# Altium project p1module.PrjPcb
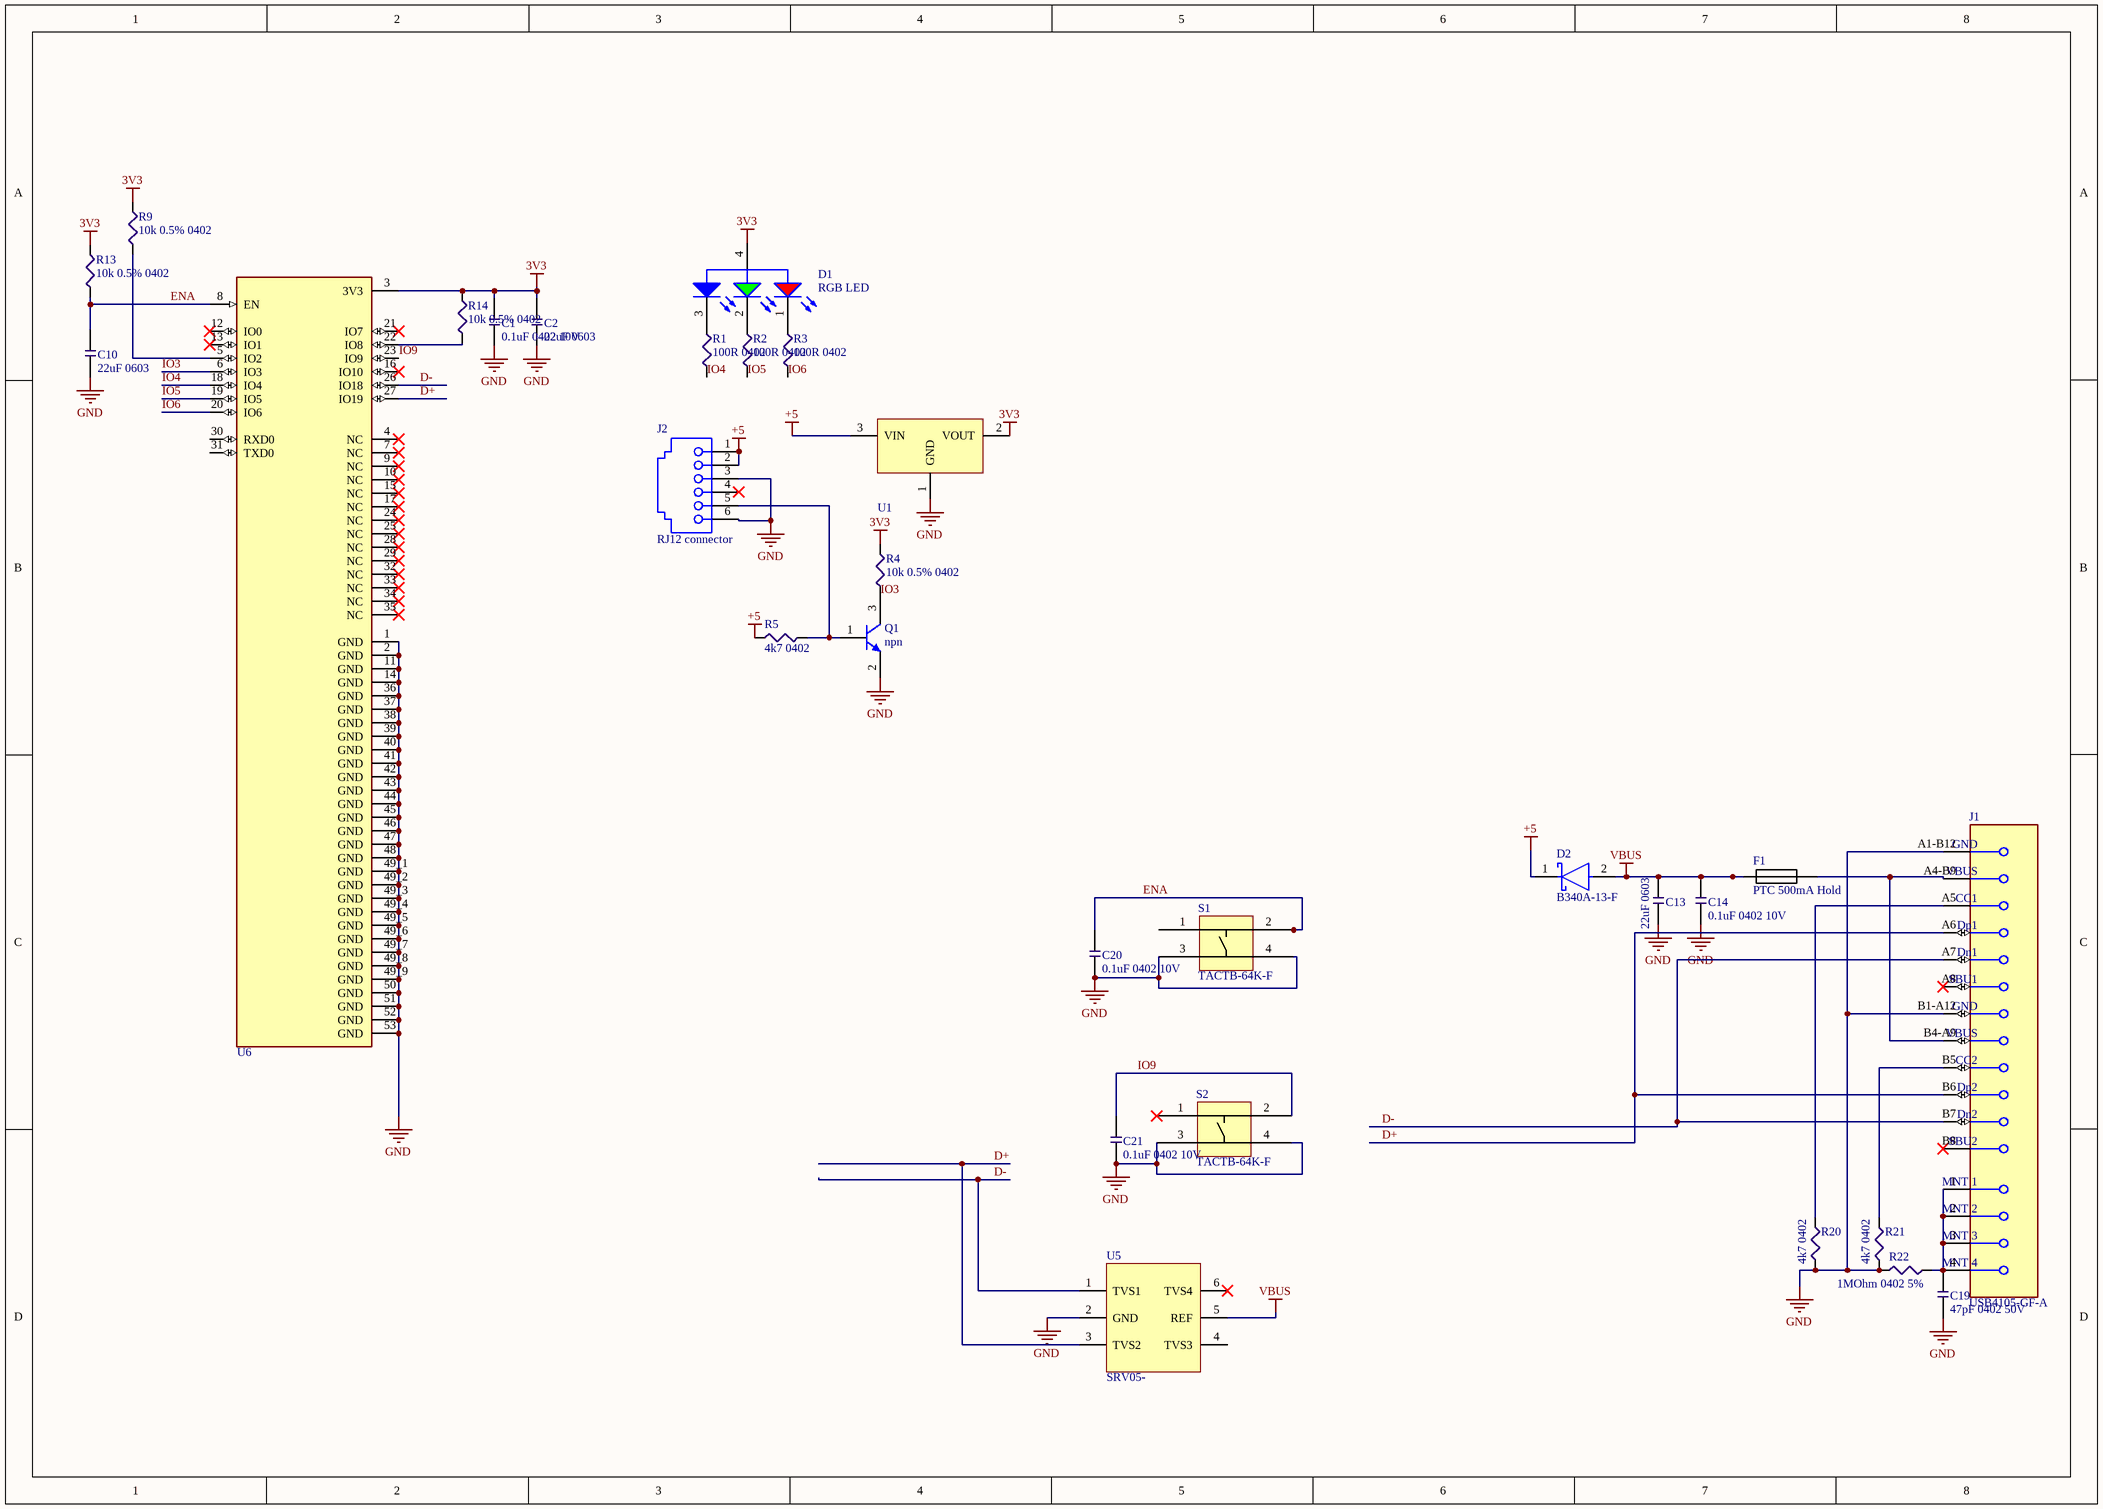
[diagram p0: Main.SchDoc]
GlobalDrawnBy: Mogens Groth Nicolaisen; GlobalProjectName: P1 Module; GlobalProjectRevision: 1.0
1 sheet, 30 parts. Net scope: hierarchical (ports join the sheet entries above them; power ports are global).
Board file: p1module.PcbDoc

## Sheet Main.SchDoc: Main
size A3; DrawnBy: Mogens Groth Nicolaisen; DocumentNumber: 1; Revision: 1.0; SheetNumber: 1; SheetTotal: 1

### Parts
C1  0.1uF 0402 10V  [CAP_0402]
C2  22uF 0603  [CAP_0603]
C10  22uF 0603  [CAP_0603]
C13  22uF 0603  [CAP_0603]
C14  0.1uF 0402 10V  [CAP_0402]
C19  47pF 0402 50V  [CAP_0402]
C20  0.1uF 0402 10V  [CAP_0402]
C21  0.1uF 0402 10V  [CAP_0402]
D1  RGB LED  [WL-SFCD_0606]
D2  B340A-13-F  [FP-SMA-MFG]
F1  PTC 500mA Hold  [PTC Fuse 1206]
J1  USB4105-GF-A  [FP-USB4105-GF-A-MFG]
J2  RJ12 connector  [615006138421]
Q1  npn  [ONSC-SOT-23-3-318-08_V]
R1  100R 0402  [RES_0402]
R2  100R 0402  [RES_0402]
R3  100R 0402  [RES_0402]
R4  10k 0.5% 0402  [RES_0402]
R5  4k7 0402  [RES_0402]
R9  10k 0.5% 0402  [RES_0402]
R13  10k 0.5% 0402  [RES_0402]
R14  10k 0.5% 0402  [RES_0402]
R20  4k7 0402  [RES_0402]
R21  4k7 0402  [RES_0402]
R22  1MOhm 0402 5%  [RES_0402]
S1  TACTB-64K-F  [TACTB-64K-F]
S2  TACTB-64K-F  [TACTB-64K-F]
U1  3.3V LDO 1A  [SOT230P700X180-4N]  (value not drawn)
U5  SRV05-  [SOT95P280X145-6N]
U6  ESP32-C3-MINI-1-N4  [ESP32-C3-MINI-1-N4-Footprint-1]  (value not drawn)

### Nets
3V3: C1.2 C2.2 D1.4(A) R4.2 R9.2 R13.2 R14.2 U1.2(VOUT) U6.3(3V3)
+5: D2.1(C) J2.1 J2.2 R5.2 U1.3(VIN)
GND: C1.1 C2.1 C10.1 C13.1 C14.1 C19.1 C20.1 C21.1 J1.A1-B12(GND) J1.B1-A12(GND) J2.3 J2.6 Q1.2(E) R20.1 R21.1 R22.1 S1.3 S1.4 S2.3 S2.4 U1.1(GND) U5.2(GND) U6.1(GND) U6.2(GND) U6.11(GND) U6.14(GND) U6.36(GND) U6.37(GND) U6.38(GND) U6.39(GND) U6.40(GND) U6.41(GND) U6.42(GND) U6.43(GND) U6.44(GND) U6.45(GND) U6.46(GND) U6.47(GND) U6.48(GND) U6.49_1(GND) U6.49_2(GND) U6.49_3(GND) U6.49_4(GND) U6.49_5(GND) U6.49_6(GND) U6.49_7(GND) U6.49_8(GND) U6.49_9(GND) U6.50(GND) U6.51(GND) U6.52(GND) U6.53(GND)
VBUS: C13.2 C14.2 D2.2(A) F1.1 U5.5(REF)
D+: J1.A6(Dp1) J1.B6(Dp2) U5.3(TVS2) U6.27(IO19)
D-: J1.A7(Dn1) J1.B7(Dn2) U5.1(TVS1) U6.26(IO18)
ENA: C10.2 C20.2 R13.1 S1.2 U6.8(EN)
IO3: Q1.3(C) R4.1 U6.6(IO3)
IO4: R1.1 U6.18(IO4)
IO5: R2.1 U6.19(IO5)
IO6: R3.1 U6.20(IO6)
IO9: C21.2 S2.2 U6.23(IO9)
NetC19_2: C19.2 J1.1(MNT_1) J1.2(MNT_2) J1.3(MNT_3) J1.4(MNT_4) R22.2
NetD1_1: D1.1(K) R3.2
NetD1_2: D1.2(K) R2.2
NetD1_3: D1.3(K) R1.2
NetF1_2: F1.2 J1.A4-B9(VBUS) J1.B4-A9(VBUS)
NetJ1_A5: J1.A5(CC1) R20.2
NetJ1_B5: J1.B5(CC2) R21.2
NetJ2_5: J2.5 Q1.1(B) R5.1
NetR9_1: R9.1 U6.5(IO2)
NetR14_1: R14.1 U6.22(IO8)

Not connected (* = marked no-connect by the designer): J1 A8(SBU1)* B8(SBU2)*; J2 4*; S1 1; S2 1*; U5 4(TVS3) 6(TVS4)*; U6 4(NC)* 7(NC)* 9(NC)* 10(NC)* 12(IO0)* 13(IO1)* 15(NC)* 16(IO10)* 17(NC)* 21(IO7)* 24(NC)* 25(NC)* 28(NC)* 29(NC)* 30(RXD0) 31(TXD0) 32(NC)* 33(NC)* 34(NC)* 35(NC)*

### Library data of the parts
C1 C14 C20 C21 = CMP-00101-1: 0.1uF 0402 10V X7R 10%; Value: 100 nF
C2 C10 C13 = CMP-00148-1: Cap Ceramic 22uF 6.3V X5R 20% SMD 0603 85C Cardboard T/R
C19 = CMP-00099-1: 47pF 0402 50V X7R 5%; Tolerance: 10%
D1 = CMP-008-0004-0.0: WL-SFCD SMT full-color Chip LED Diffused; Forward Current: 20mA; Forward Voltage: 3.3V; Luminous Intensity: 900mcd; Viewing Angle: 120°
D2 = CMP-016-0019-1: Rectifier Diode, Schottky, 1 Phase, 1 Element, 3A, 40V V(RRM), Silicon; Capacitance: 250pF; Element Configuration: Single; Forward Voltage: 500mV; Max Forward Surge Current (Ifsm): 80A; Max Reverse Current: 500uA; Polarity: Standard
F1 = CMP-017-0001-1: PTC RESET FUSE 8V 500MA 1206; Mfg. Part Number: 0ZCJ0050FF2G
J1 = CMP-003-0034-0.0: Conn USB 2.0 Type C RCP 24 POS 0.3mm/0.5mm Solder RA SMD 24 Terminal 1 Port T/R; Gender: Receptacle; Mating Cycles: 10000; Number of Ports: 1; Shielding: Shielded
J2 = CMP-003-0042-0.0: Telecom and Datacom Connector, 6 Contact(s), Male, Right Angle, Solder Terminal, Locking, Receptacle; Connector Type: Jack; Current Rating: 1.5A; Direction: Up; Gender: Female; Insulation Resistance: 500MR; Mating Cycles: 500; Number of Contacts: 6; Number of Ports: 1; Shielding: Unshielded; Voltage Rating (AC): 120V
Q1 = CMP-014-0017-1: NPN 40V 0.2A SOT23; Collector Base Voltage (VCBO): 80V; Collector Emitter Breakdown Voltage: 65V; Collector Emitter Saturation Voltage: 600mV; Current Rating: 100mA; Element Configuration: Single; Emitter Base Voltage (VEBO): 6V; Frequency: 100MHz; Max Power Dissipation: 300mW; Number of Elements: 1; hFE Min: 200
R1-R3 = CMP-001-0001-5: 100R 1% 0402 63mW
R4 R9 R13 R14 = CMP-0001-00029-2: RES 10K OHM 0.5% 1/16W 0402; Manufacturer Part No.: RC0402DR-0710KL
R5 R20 R21 = CMP-001-0029-3: RES SMD 4.7K OHM 1% 1/16W 0402; Mfg. Part Number: RC1005F472CS; Tolerance: 1
R22 = CMP-001-0065-1: RES SMD 1M OHM 5% 1/16W 0402; Mfg. Part Number: CR0402JC1MS001; Value: 1Mega
S1 S2 = CMP-013-0002-1: Microswitch TACT; SPST-NO; Positions:2; 0.05A/12VDC;
U1 = CMP-00114-2: IC REG LINEAR 3.3V 1A SOT223; Dropout Voltage: 1.1V; Number of Regulators: 1; Max Input Voltage: 13V; Operating Supply Current: 3.5mA; Power Supply Rejection Ratio (PSRR): 70dB; Polarity: Positive; Accuracy: 1%; Reference Voltage: 1.262V; Output Type: Fixed
U5 = CMP-016-0020-1: SRV05 Series 4 Ch 3.5 pF 15 Vclamp Steering Diode/TVS Array Combo - SOT-23-6; Capacitance: 3.5pF; Clamping Voltage: 15V; Direction: Unidirectional; Leakage Current: 5uA; Number of Channels: 4; Number of Elements: 1; Peak Pulse Current: 5A; Peak Pulse Power: 500W; Reverse Breakdown Voltage: 6V; Reverse Standoff Voltage: 5V; Test Current: 1mA
U6 = CMP-00162-1: Bluetooth, WiFi 802.11b/g/n, Bluetooth v5.0 Transceiver Module 2.412GHz ~ 2.484GHz PCB Trace Surface Mount

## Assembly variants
Default: not fitted J1 PL2 PL2 PL3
